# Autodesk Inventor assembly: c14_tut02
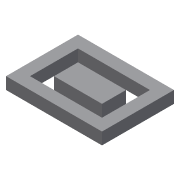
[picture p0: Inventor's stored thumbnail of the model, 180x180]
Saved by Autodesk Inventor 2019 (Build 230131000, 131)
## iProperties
Created: 2010-04
Part Number: c14_tut02
Document SubType Name: Assembly
Designer: CADSoft
Author: CADSoft
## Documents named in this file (3)
- E:\_Deepak\Inventor\Projects\Autodesk Inventor_2019_Project\Resources\Inventor_2018_tut\c18_Inv_2019_tut\c18_Inv_tut_2019\c18_tut02_inv\c18_tut02_inv.iam
- E:\_Deepak\Inventor\Projects\Autodesk Inventor_2019_Project\Resources\Inventor_2018_tut\c18_Inv_2019_tut\c18_Inv_tut_2019\c18_tut02_inv\Outer Plate.ipt
- E:\_Deepak\Inventor\Projects\Autodesk Inventor_2019_Project\Resources\Inventor_2018_tut\c18_Inv_2019_tut\c18_Inv_tut_2019\c18_tut02_inv\Inner Plate.ipt
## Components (2 placed, 2 different names)
1. Outer Plate:1 — Flush:1, Flush:2, Mate:1, Mate:2, Mate:3, Mate:4
2. Inner Plate:1 — Flush:1, Flush:2, Mate:1, Mate:2, Mate:3, Mate:4
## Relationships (6: Mate 4, Flush 2)
- Flush:1: Outer Plate:1 ↔ Inner Plate:1
- Flush:2: Outer Plate:1 ↔ Inner Plate:1
- Mate:1: Outer Plate:1 ↔ Inner Plate:1
- Mate:2: Outer Plate:1 ↔ Inner Plate:1
- Mate:3: Outer Plate:1 ↔ Inner Plate:1
- Mate:4: Outer Plate:1 ↔ Inner Plate:1
